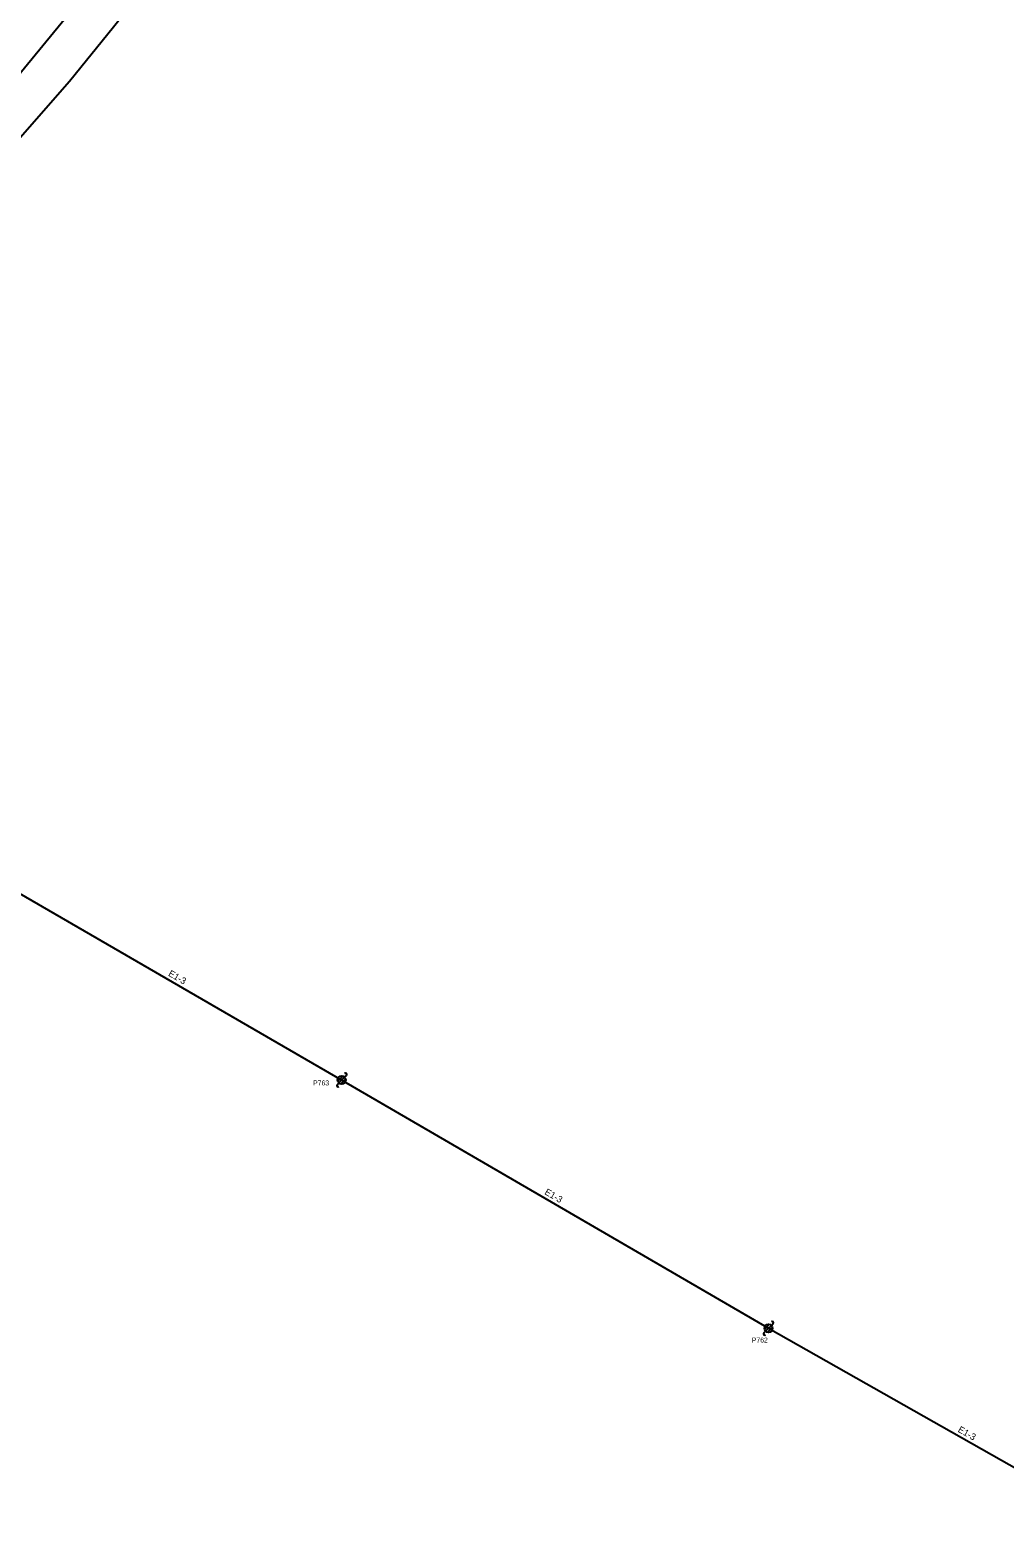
# Model space of a CAD drawing. Extents: x 1741604 to 1825760, y 1164229 to 1194908.
# Drawn here: x 1772457 to 1773048, y 1180257 to 1181171 of the extents above; entities that cross this region are included whole.
import ezdxf

# ---------------------------------------------------------------- set-up
doc = ezdxf.new("R2010")
doc.units = 0
for name, color, linetype in [('RD_EX_SU_H2O', 7, 'Continuous'), ('RD_EX_SU_Ovhd', 7, 'Continuous'), ('RD_EX_SU_Pole', 7, 'Continuous'), ('RD_EX_SU_Telecom', 7, 'Continuous'), ('RD_EX_SU_TX_Pole', 7, 'Continuous')]:
    doc.layers.add(name, color=color, linetype=linetype)

# ---------------------------------------------------------------- blocks, each defined once
blk = doc.blocks.new('SUE_PP')
at = {"layer": 'RD_EX_SU_Pole'}
for p, q in [((-2.41, -0.65), (0.65, 2.41)), ((-1.77, -1.77), (1.77, 1.77)), ((-0.65, -2.41), (2.41, 0.65)), ((1.77, 1.77), (2.83, 2.83)), ((-2.83, -2.83), (-1.77, -1.77))]:
    blk.add_line(p, q, dxfattribs=at)
blk.add_circle((0, 0), 2.5, dxfattribs=at)
for centre, start, end in [((2.3, 3.36), 315, 135), ((-2.3, -3.36), 135, 315)]:
    blk.add_arc(centre, 0.75, start, end, dxfattribs=at)

msp = doc.modelspace()

# ---------------------------------------------------------------- linework, layer by layer
at = {"layer": 'RD_EX_SU_H2O'}
msp.add_lwpolyline([(1772113.57, 1180765.54), (1772228.62, 1180895.12), (1772343.42, 1181022.45), (1772442.26, 1181134.91), (1772535.84, 1181249.02), (1772563.53, 1181288.52), (1772591.62, 1181328.82), (1772640.34, 1181415.41), (1772682.27, 1181505.27), (1772700.74, 1181551.33), (1772738.36, 1181647.58), (1772786.7, 1181777.24)], dxfattribs=at)
at = {"layer": 'RD_EX_SU_Ovhd'}
for p, q in [((1772401.4, 1180676.27), (1772645.63, 1180534.74)), ((1772645.63, 1180534.74), (1772904.3, 1180384.23)), ((1772904.3, 1180384.23), (1773128.45, 1180257.18))]:
    msp.add_line(p, q, dxfattribs=at)
at = {"layer": 'RD_EX_SU_Telecom'}
msp.add_lwpolyline([(1772091.89, 1180684.87), (1772087.11, 1180686.29), (1772086.52, 1180688.08), (1772088.93, 1180693.62), (1772096.91, 1180706.61), (1772105.42, 1180718.77), (1772144.04, 1180764.5), (1772183.39, 1180808.36), (1772231.73, 1180862.02), (1772268.62, 1180902.51), (1772293.18, 1180930.86), (1772330.2, 1180972.4), (1772359.62, 1181003.89), (1772393.58, 1181042.3), (1772439.39, 1181093.24), (1772480.57, 1181140.31), (1772507.32, 1181173.35), (1772546.01, 1181222.2), (1772609.98, 1181309.67), (1772659.45, 1181393.41), (1772700.65, 1181486.4), (1772715.32, 1181519.93), (1772719.6, 1181522.19), (1772730.27, 1181518.08)], dxfattribs=at)

# ---------------------------------------------------------------- block references
at = {"layer": 'RD_EX_SU_Pole'}
for p in [(1772645.63, 1180534.74), (1772904.3, 1180384.23)]:
    msp.add_blockref('SUE_PP', p, dxfattribs=at)

# ---------------------------------------------------------------- texts
at = {"layer": 'RD_EX_SU_Ovhd'}
for rotation, p in [(329.90775, (1772540.14, 1180598.18)), (329.80647, (1772768.2, 1180465.73)), (330.45543, (1773018.74, 1180321.66))]:
    msp.add_text('E1-3', height=4, rotation=rotation, dxfattribs=at).set_placement(p)
at = {"layer": 'RD_EX_SU_TX_Pole'}
for s, p in [('P763', (1772628.3, 1180531.48)), ('P762', (1772894.22, 1180375.59))]:
    msp.add_text(s, height=3, dxfattribs=at).set_placement(p)

doc.saveas('drawing.dxf')
